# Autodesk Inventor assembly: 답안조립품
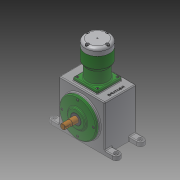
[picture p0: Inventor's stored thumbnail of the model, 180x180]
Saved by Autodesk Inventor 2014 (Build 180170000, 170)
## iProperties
Created: 2016-11
Part Number: 답안조립품
Document SubType Name: Assembly
Designer: NET
Author: NET
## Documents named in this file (16)
- C:\Users\NET\Desktop\361107V1021\답안조립품.iam
- C:\Users\NET\Desktop\361107V1021\본체.ipt
- C:\Users\NET\Desktop\361107V1021\메인크랭크축.ipt
- C:\Users\NET\Desktop\361107V1021\베어링 20 x 47 x 14.ipt
- C:\Users\NET\Desktop\361107V1021\베어링 NA 4902.ipt
- C:\Users\NET\Desktop\361107V1021\볼트 M4 x 8.ipt
- C:\Users\NET\Desktop\361107V1021\볼트 M5 x 20.ipt
- C:\Users\NET\Desktop\361107V1021\실린더.ipt
- C:\Users\NET\Desktop\361107V1021\실린더헤드.ipt
- C:\Users\NET\Desktop\361107V1021\앞커버.ipt
- C:\Users\NET\Desktop\361107V1021\오일 실 20 35 8.ipt
- C:\Users\NET\Desktop\361107V1021\커넥팅로드.ipt
- C:\Users\NET\Desktop\361107V1021\크랭크보조축.ipt
- C:\Users\NET\Desktop\361107V1021\피스톤.ipt
- C:\Users\NET\Desktop\361107V1021\피스톤핀.ipt
- C:\Users\NET\Desktop\361107V1021\가변스프링.ipt
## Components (15 placed, 5 different names)
1. 피스톤:1
2. 피스톤핀:1
3. ISO 4762 M4 x 8:5
4. ISO 4762 M4 x 8:6
5. ISO 4762 M4 x 8:7
6. ISO 4762 M4 x 8:8
7. 가변스프링:1
8. ISO 4762 M5 x 20:1
9. ISO 4762 M5 x 20:2
10. ISO 4762 M5 x 20:3
11. ISO 4762 M5 x 20:4
12. ISO 4762 M4 x 8:1
13. ISO 4762 M4 x 8:2
14. ISO 4762 M4 x 8:3
15. ISO 4762 M4 x 8:4
